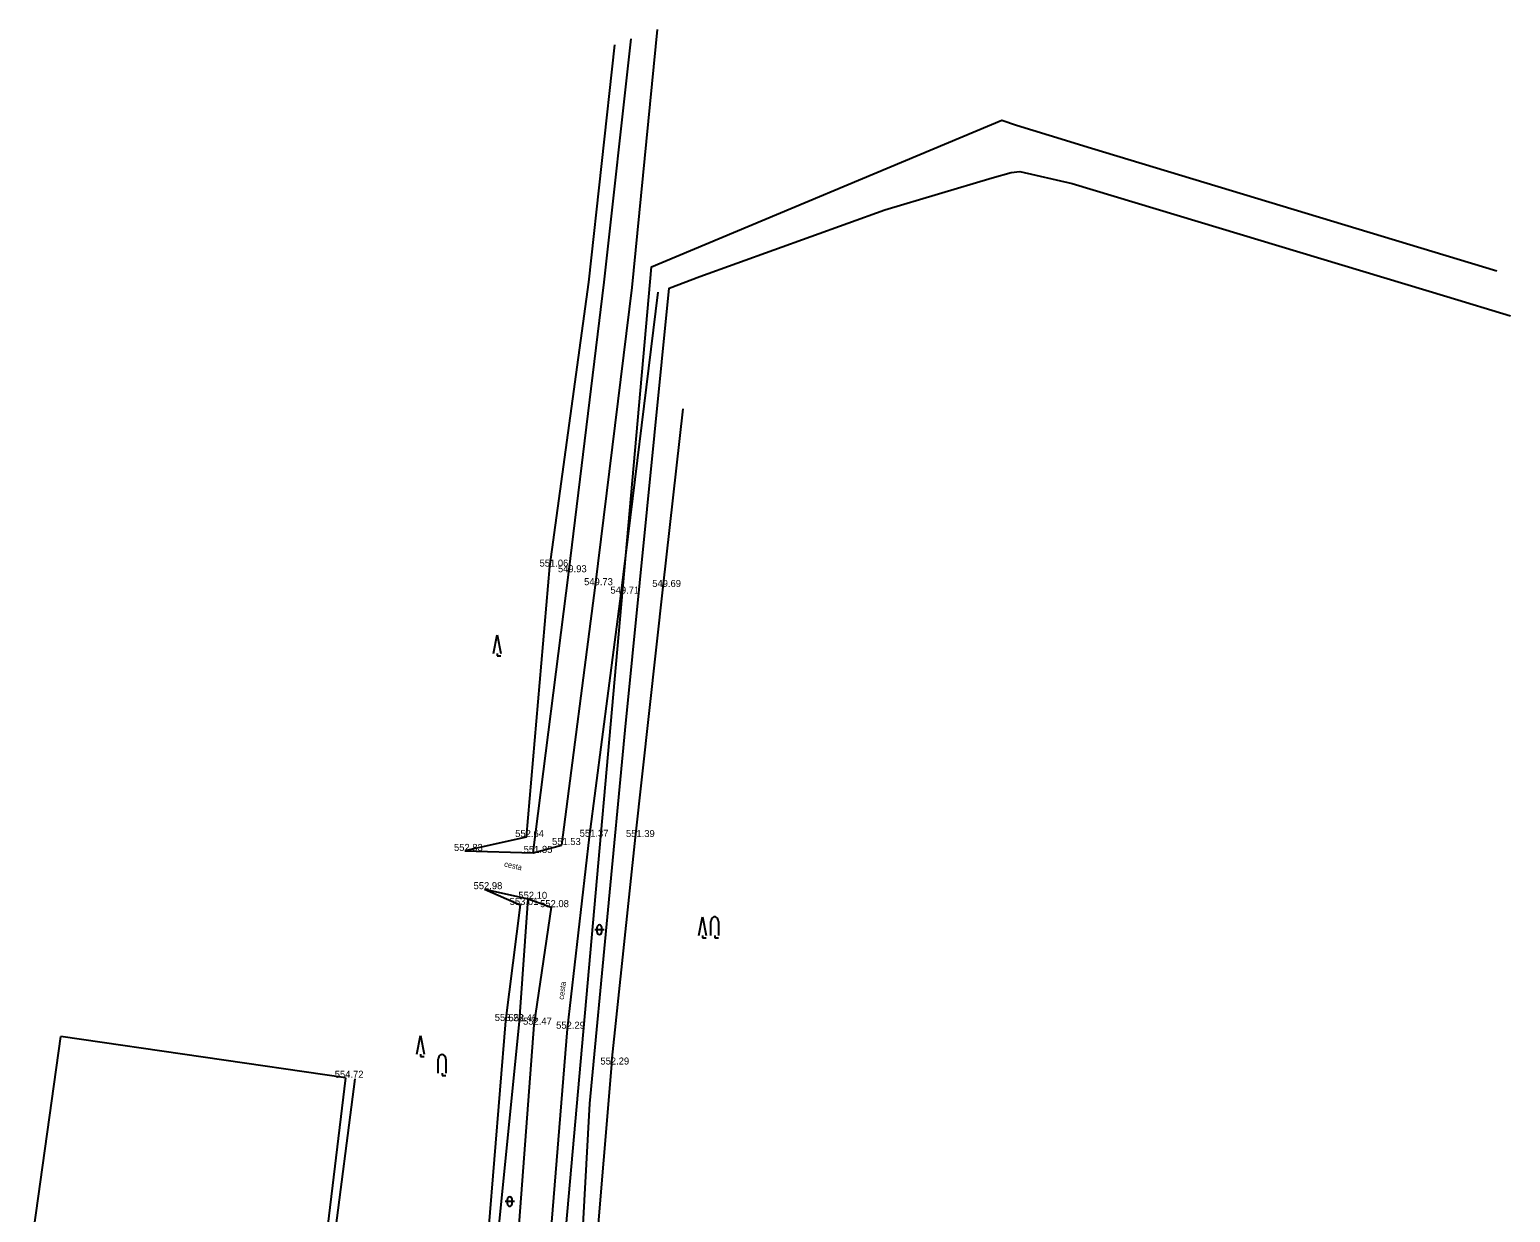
# Model space of a CAD drawing. Extents: x -669393 to -668650, y -1126925 to -1126294.
# Drawn here: x -668961.3 to -668803.3, y -1126420.4 to -1126294.2 of the extents above; entities that cross this region are included whole.
import ezdxf

# ---------------------------------------------------------------- set-up
doc = ezdxf.new("R2010")
doc.units = 0
for name, color, linetype in [('G_Bod_tecka', 7, 'Continuous'), ('G_Bod_vyska', 7, 'Continuous'), ('G_Breh_Teren', 7, 'Continuous'), ('G_Cesty_Schody', 7, 'Continuous'), ('G_Ploty', 7, 'Continuous'), ('G_Popisy_povrchu', 7, 'Continuous'), ('G_Z_SPOJE_podz_geodeticky', 7, 'Continuous'), ('G_Z_SPOJE_podz_priblizne', 7, 'Continuous'), ('G_Zelen-rozhrani', 7, 'Continuous'), ('G_Zelen-Znacky', 7, 'Continuous')]:
    doc.layers.add(name, color=color, linetype=linetype)

msp = doc.modelspace()

# ---------------------------------------------------------------- linework, layer by layer
at = {"layer": 'G_Bod_tecka'}
for p, q in [((-668905.82, -1126351.52), (-668905.82, -1126351.52)), ((-668903.75, -1126352.12), (-668903.75, -1126352.12)), ((-668900.96, -1126353.5), (-668900.96, -1126353.5)), ((-668893.68, -1126353.69), (-668893.68, -1126353.69)), ((-668898.22, -1126354.4), (-668898.22, -1126354.4)), ((-668908.3, -1126380.37), (-668908.3, -1126380.37)), ((-668901.58, -1126380.34), (-668901.58, -1126380.34)), ((-668896.64, -1126380.37), (-668896.64, -1126380.37)), ((-668914.85, -1126381.85), (-668914.85, -1126381.85)), ((-668907.56, -1126382.06), (-668907.56, -1126382.06)), ((-668904.53, -1126381.22), (-668904.53, -1126381.22)), ((-668912.75, -1126385.93), (-668912.75, -1126385.93)), ((-668908.1, -1126386.96), (-668908.1, -1126386.96)), ((-668908.95, -1126387.61), (-668908.95, -1126387.61)), ((-668905.63, -1126387.85), (-668905.63, -1126387.85)), ((-668910.5, -1126399.99), (-668910.5, -1126399.99)), ((-668909.02, -1126400.02), (-668909.02, -1126400.02)), ((-668907.48, -1126400.39), (-668907.48, -1126400.39)), ((-668903.94, -1126400.82), (-668903.94, -1126400.82)), ((-668899.22, -1126404.64), (-668899.22, -1126404.64)), ((-668927.57, -1126406.05), (-668927.57, -1126406.05))]:
    msp.add_line(p, q, dxfattribs=at)
at = {"layer": 'G_Breh_Teren'}
for points in [[(-668907.56, -1126382.06), (-668903.75, -1126352.12), (-668900, -1126321.17), (-668897.09, -1126295.22)], [(-668898.9, -1126295.87), (-668901.65, -1126321.17), (-668905.82, -1126351.52), (-668908.3, -1126380.37), (-668914.85, -1126381.85)], [(-668912.75, -1126385.93), (-668908.95, -1126387.61), (-668910.5, -1126399.99), (-668912.33, -1126422.17)], [(-668911.25, -1126422.45), (-668909.02, -1126400.02), (-668908.1, -1126386.96)]]:
    msp.add_lwpolyline(points, dxfattribs=at)
at = {"layer": 'G_Cesty_Schody'}
for points in [[(-668894.32, -1126294.23), (-668897.04, -1126321.76), (-668900.96, -1126353.5), (-668904.53, -1126381.22)], [(-668894.26, -1126322.24), (-668898.22, -1126354.4), (-668901.58, -1126380.34), (-668903.94, -1126400.82), (-668905.92, -1126425.4)], [(-668914.85, -1126381.85), (-668907.56, -1126382.06), (-668904.53, -1126381.22)], [(-668912.75, -1126385.93), (-668908.1, -1126386.96), (-668905.63, -1126387.85)], [(-668905.63, -1126387.85), (-668907.48, -1126400.39), (-668909.37, -1126425.55)]]:
    msp.add_lwpolyline(points, dxfattribs=at)
at = {"layer": 'G_Ploty'}
for p, q in [((-668961.28, -1126425.45), (-668957.94, -1126401.66)), ((-668927.57, -1126406.05), (-668957.94, -1126401.66)), ((-668927.57, -1126406.05), (-668929.94, -1126425.45))]:
    msp.add_line(p, q, dxfattribs=at)
at = {"layer": 'G_Z_SPOJE_podz_geodeticky'}
for points in [[(-668931.17, -1126436.55), (-668905.21, -1126435.1), (-668894.94, -1126319.53), (-668857.57, -1126303.9), (-668856.01, -1126304.41), (-668852.51, -1126305.5)], [(-668852.51, -1126305.5), (-668848.01, -1126306.87), (-668804.76, -1126319.97)], [(-668913.11, -1126502.62), (-668907.04, -1126482.44), (-668904.52, -1126474.93), (-668904.4, -1126467.75), (-668903.38, -1126442.44), (-668901.53, -1126408.78), (-668897.76, -1126368.98), (-668893.07, -1126321.82), (-668889.79, -1126320.56), (-668870.03, -1126313.47), (-668858.58, -1126310.04), (-668856.57, -1126309.46), (-668855.65, -1126309.36)], [(-668855.65, -1126309.36), (-668850.08, -1126310.65), (-668810.08, -1126322.7), (-668803.31, -1126324.76)]]:
    msp.add_lwpolyline(points, dxfattribs=at)
at = {"layer": 'G_Z_SPOJE_podz_priblizne'}
for points in [[(-668931.17, -1126436.55), (-668905.21, -1126435.1), (-668894.94, -1126319.53), (-668857.57, -1126303.9), (-668856.01, -1126304.41), (-668852.51, -1126305.5)], [(-668852.51, -1126305.5), (-668848.01, -1126306.87), (-668804.76, -1126319.97)], [(-668913.11, -1126502.62), (-668907.04, -1126482.44), (-668904.52, -1126474.93), (-668904.4, -1126467.75), (-668903.38, -1126442.44), (-668901.53, -1126408.78), (-668897.76, -1126368.98), (-668893.07, -1126321.82), (-668889.79, -1126320.56), (-668870.03, -1126313.47), (-668858.58, -1126310.04), (-668856.57, -1126309.46), (-668855.65, -1126309.36)], [(-668855.65, -1126309.36), (-668850.08, -1126310.65), (-668810.08, -1126322.7), (-668803.31, -1126324.76)]]:
    msp.add_lwpolyline(points, dxfattribs=at)
at = {"layer": 'G_Zelen-rozhrani'}
msp.add_line((-668926.58, -1126406.17), (-668928.9, -1126424), dxfattribs=at)
for points in [[(-668893.68, -1126353.69), (-668891.56, -1126334.7)], [(-668896.64, -1126380.37), (-668893.68, -1126353.69)], [(-668899.22, -1126404.64), (-668896.64, -1126380.37)], [(-668899.22, -1126404.64), (-668902.63, -1126445.45)]]:
    msp.add_lwpolyline(points, dxfattribs=at)
at = {"layer": 'G_Zelen-Znacky'}
for points in [[(-668911.8, -1126360.79), (-668911.4, -1126358.79)], [(-668911.4, -1126358.79), (-668911, -1126360.79)], [(-668911.4, -1126360.79), (-668911.4, -1126361.04)], [(-668911.4, -1126361.04), (-668911, -1126361.04)], [(-668889.89, -1126390.87), (-668889.49, -1126388.87)], [(-668889.49, -1126388.87), (-668889.09, -1126390.87)], [(-668899.99, -1126390.25), (-668900.99, -1126390.25)], [(-668900.74, -1126390.5), (-668900.74, -1126390)], [(-668900.24, -1126390.5), (-668900.24, -1126390)], [(-668888.6, -1126390.87), (-668888.6, -1126389.37)], [(-668887.8, -1126389.37), (-668887.8, -1126390.87)], [(-668889.49, -1126390.87), (-668889.49, -1126391.12)], [(-668889.49, -1126391.12), (-668889.09, -1126391.12)], [(-668888.2, -1126390.87), (-668888.2, -1126391.12)], [(-668888.2, -1126391.12), (-668887.8, -1126391.12)], [(-668919.98, -1126403.53), (-668919.58, -1126401.53)], [(-668919.58, -1126401.53), (-668919.18, -1126403.53)], [(-668919.58, -1126403.53), (-668919.58, -1126403.78)], [(-668919.58, -1126403.78), (-668919.18, -1126403.78)], [(-668917.68, -1126405.57), (-668917.68, -1126404.07)], [(-668916.88, -1126404.07), (-668916.88, -1126405.57)], [(-668917.28, -1126405.57), (-668917.28, -1126405.82)], [(-668917.28, -1126405.82), (-668916.88, -1126405.82)], [(-668909.56, -1126419.25), (-668910.56, -1126419.25)], [(-668910.31, -1126419.5), (-668910.31, -1126419)], [(-668909.81, -1126419.5), (-668909.81, -1126419)]]:
    msp.add_lwpolyline(points, dxfattribs=at)
for centre, start, end in [((-668900.49, -1126390), 0, 180), ((-668900.49, -1126390.5), 180, 0), ((-668910.06, -1126419), 0, 180), ((-668910.06, -1126419.5), 180, 0)]:
    msp.add_arc(centre, 0.25, start, end, dxfattribs=at)
for centre in [(-668888.2, -1126389.37), (-668917.28, -1126404.07)]:
    msp.add_ellipse(centre, major_axis=(0, 0.5), ratio=0.8, start_param=4.712389, end_param=7.853982, dxfattribs=at)

# ---------------------------------------------------------------- texts
at = {"layer": 'G_Bod_vyska'}
for s, p in [('551.06', (-668906.88, -1126351.52)), ('549.93', (-668904.92, -1126352.12)), ('549.73', (-668902.13, -1126353.5)), ('549.71', (-668899.32, -1126354.4)), ('549.69', (-668894.86, -1126353.69)), ('552.64', (-668909.48, -1126380.37)), ('551.53', (-668905.55, -1126381.22)), ('551.37', (-668902.6, -1126380.34)), ('551.39', (-668897.66, -1126380.37)), ('552.83', (-668916.01, -1126381.85)), ('551.85', (-668908.58, -1126382.06)), ('552.98', (-668913.92, -1126385.93)), ('553.01', (-668910.07, -1126387.61)), ('552.10', (-668909.14, -1126386.96)), ('552.08', (-668906.82, -1126387.85)), ('553.28', (-668911.66, -1126399.99)), ('552.46', (-668910.2, -1126400.02)), ('552.47', (-668908.64, -1126400.39)), ('552.29', (-668905.11, -1126400.82)), ('552.29', (-668900.39, -1126404.64)), ('554.72', (-668928.73, -1126406.05))]:
    msp.add_text(s, height=0.75, dxfattribs=at).set_placement(p)
at = {"layer": 'G_Popisy_povrchu'}
for rotation, p in [(347.5103, (-668910.7, -1126383.51)), (83.4266, (-668904.29, -1126397.74))]:
    msp.add_text('cesta', height=0.6, rotation=rotation, dxfattribs=at).set_placement(p)

doc.saveas('drawing.dxf')
